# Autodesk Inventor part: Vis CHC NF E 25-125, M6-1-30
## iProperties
Shininess: 64.0
Length Units: 11269
Angle Units: 11279
Time Units: 11290
Mass Units: 11283
Length Display Precision: 3
Angle Display Precision: 2
Compacted: True
Part Number: Vis CHC NF E 25-125, M6-1-30
Document SubType Name: Modeling
Created: 2005-02
Material: Par défaut
Designer: LEGERET Philippe
Catalog Web Link: www.traceparts.com
Description: Vis CHC M6-1-30 - 4,8, Grade A, type 1 - NF E 25-125
Density: 0.0
Volumn: 0.0
Area: 0.0
PropertySet Name: Model Information
Control State: 0
Master: False
Checked Out: False
Author: Trace Parts S.A.
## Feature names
1. Base1
